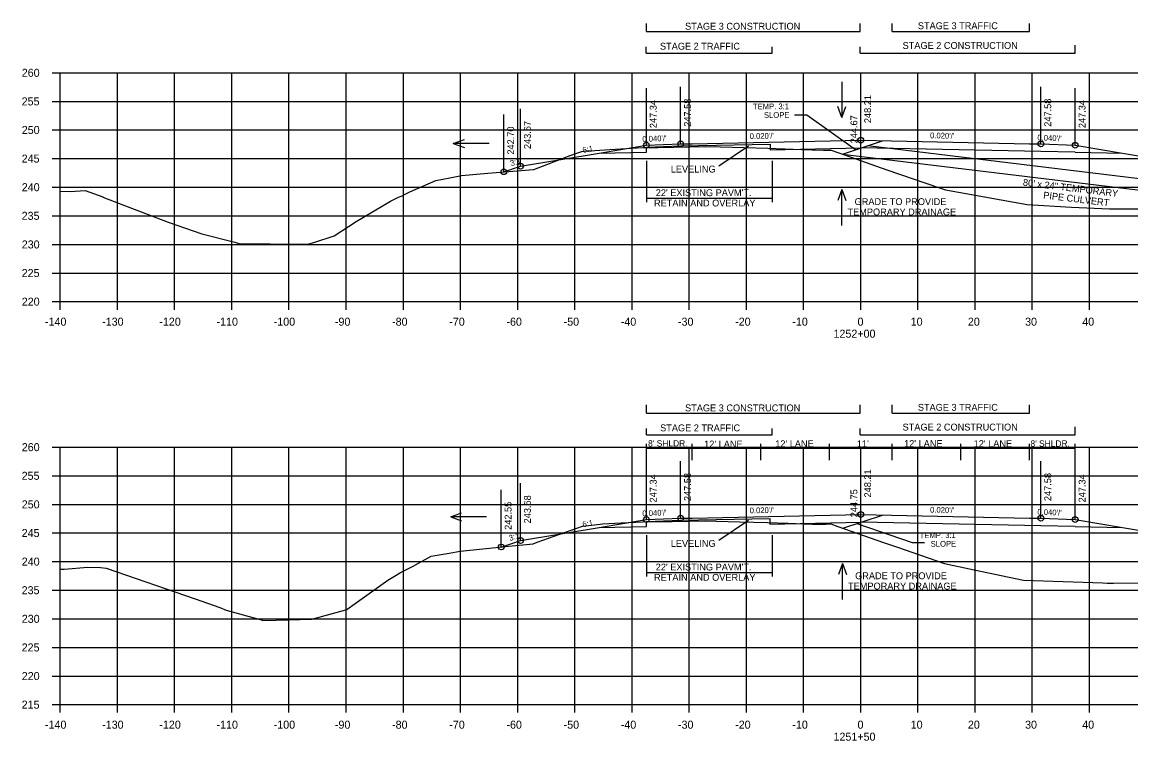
# Model space of a CAD drawing. Extents: x 1342547 to 1344156, y -1532351 to -1517216.
# Drawn here: x 1342556.2 to 1342750.1, y -1527004 to -1526878.4 of the extents above; entities that cross this region are included whole.
import ezdxf

# ---------------------------------------------------------------- set-up
doc = ezdxf.new("R2010")
doc.units = 0
for name, color, linetype in [('R_Alt Surface', 7, 'Continuous'), ('R_Axis', 7, 'Continuous'), ('R_Axis Annot', 7, 'Continuous'), ('R_Draft', 7, 'Continuous'), ('R_Exist Surface', 7, 'Continuous'), ('R_Fin Surface', 7, 'Continuous'), ('R_Grid', 7, 'Continuous'), ('R_No Plot', 7, 'Continuous'), ('R_Water', 7, 'Continuous'), ('R_Xsect Elev', 7, 'Continuous'), ('R_Xsect Slope', 7, 'Continuous')]:
    doc.layers.add(name, color=color, linetype=linetype)

msp = doc.modelspace()

# ---------------------------------------------------------------- linework, layer by layer
at = {"layer": 'R_Alt Surface'}
for points in [[(1342665.37, -1526901.15), (1342665.37, -1526900.27), (1342671.37, -1526900.03), (1342687, -1526899.72)], [(1342687, -1526899.72), (1342687, -1526900.72), (1342702.87, -1526900.4)], [(1342740.37, -1526901.15), (1342734.37, -1526901.03), (1342702.87, -1526900.4)], [(1342657.09, -1526901.31), (1342665.37, -1526901.15)], [(1342740.37, -1526901.15), (1342748.64, -1526901.31)], [(1342657.09, -1526966.73), (1342665.37, -1526966.57)], [(1342665.37, -1526966.57), (1342665.37, -1526965.69), (1342671.37, -1526965.45), (1342686.99, -1526965.14)], [(1342686.99, -1526965.14), (1342686.99, -1526966.14), (1342702.87, -1526965.82)], [(1342740.37, -1526966.57), (1342734.37, -1526966.45), (1342702.87, -1526965.82)], [(1342740.37, -1526966.57), (1342748.64, -1526966.73)]]:
    msp.add_lwpolyline(points, dxfattribs=at)
at = {"layer": 'R_Axis'}
for p, q in [((1342561.47, -1526887.27), (1342562.87, -1526887.27)), ((1342562.87, -1526927.27), (1342562.87, -1526887.27)), ((1342561.47, -1526892.27), (1342562.87, -1526892.27)), ((1342561.47, -1526897.27), (1342562.87, -1526897.27)), ((1342561.47, -1526902.27), (1342562.87, -1526902.27)), ((1342561.47, -1526907.27), (1342562.87, -1526907.27)), ((1342561.47, -1526912.27), (1342562.87, -1526912.27)), ((1342561.47, -1526917.27), (1342562.87, -1526917.27)), ((1342561.47, -1526922.27), (1342562.87, -1526922.27)), ((1342561.47, -1526927.27), (1342562.87, -1526927.27)), ((1342562.87, -1526927.27), (1342842.87, -1526927.27)), ((1342562.87, -1526928.67), (1342562.87, -1526927.27)), ((1342572.87, -1526928.67), (1342572.87, -1526927.27)), ((1342582.87, -1526928.67), (1342582.87, -1526927.27)), ((1342592.87, -1526928.67), (1342592.87, -1526927.27)), ((1342602.87, -1526928.67), (1342602.87, -1526927.27)), ((1342612.87, -1526928.67), (1342612.87, -1526927.27)), ((1342622.87, -1526928.67), (1342622.87, -1526927.27)), ((1342632.87, -1526928.67), (1342632.87, -1526927.27)), ((1342642.87, -1526928.67), (1342642.87, -1526927.27)), ((1342652.87, -1526928.67), (1342652.87, -1526927.27)), ((1342662.87, -1526928.67), (1342662.87, -1526927.27)), ((1342672.87, -1526928.67), (1342672.87, -1526927.27)), ((1342682.87, -1526928.67), (1342682.87, -1526927.27)), ((1342692.87, -1526928.67), (1342692.87, -1526927.27)), ((1342702.87, -1526928.67), (1342702.87, -1526927.27)), ((1342712.87, -1526928.67), (1342712.87, -1526927.27)), ((1342722.87, -1526928.67), (1342722.87, -1526927.27)), ((1342732.87, -1526928.67), (1342732.87, -1526927.27)), ((1342742.87, -1526928.67), (1342742.87, -1526927.27)), ((1342561.47, -1526952.7), (1342562.87, -1526952.7)), ((1342562.87, -1526997.7), (1342562.87, -1526952.7)), ((1342561.47, -1526957.7), (1342562.87, -1526957.7)), ((1342561.47, -1526962.7), (1342562.87, -1526962.7)), ((1342561.47, -1526967.7), (1342562.87, -1526967.7)), ((1342561.47, -1526972.7), (1342562.87, -1526972.7)), ((1342561.47, -1526977.7), (1342562.87, -1526977.7)), ((1342561.47, -1526982.7), (1342562.87, -1526982.7)), ((1342561.47, -1526987.7), (1342562.87, -1526987.7)), ((1342561.47, -1526992.7), (1342562.87, -1526992.7)), ((1342561.47, -1526997.7), (1342562.87, -1526997.7)), ((1342562.87, -1526997.7), (1342842.87, -1526997.7)), ((1342562.87, -1526999.1), (1342562.87, -1526997.7)), ((1342572.87, -1526999.1), (1342572.87, -1526997.7)), ((1342582.87, -1526999.1), (1342582.87, -1526997.7)), ((1342592.87, -1526999.1), (1342592.87, -1526997.7)), ((1342602.87, -1526999.1), (1342602.87, -1526997.7)), ((1342612.87, -1526999.1), (1342612.87, -1526997.7)), ((1342622.87, -1526999.1), (1342622.87, -1526997.7)), ((1342632.87, -1526999.1), (1342632.87, -1526997.7)), ((1342642.87, -1526999.1), (1342642.87, -1526997.7)), ((1342652.87, -1526999.1), (1342652.87, -1526997.7)), ((1342662.87, -1526999.1), (1342662.87, -1526997.7)), ((1342672.87, -1526999.1), (1342672.87, -1526997.7)), ((1342682.87, -1526999.1), (1342682.87, -1526997.7)), ((1342692.87, -1526999.1), (1342692.87, -1526997.7)), ((1342702.87, -1526999.1), (1342702.87, -1526997.7)), ((1342712.87, -1526999.1), (1342712.87, -1526997.7)), ((1342722.87, -1526999.1), (1342722.87, -1526997.7)), ((1342732.87, -1526999.1), (1342732.87, -1526997.7)), ((1342742.87, -1526999.1), (1342742.87, -1526997.7))]:
    msp.add_line(p, q, dxfattribs=at)
at = {"layer": 'R_Draft'}
for p, q in [((1342665.37, -1526880.06), (1342665.37, -1526878.63)), ((1342702.78, -1526880.06), (1342702.78, -1526878.63)), ((1342708.37, -1526880.06), (1342708.37, -1526878.63)), ((1342732.37, -1526880.06), (1342732.37, -1526878.63)), ((1342665.37, -1526880.06), (1342702.78, -1526880.06)), ((1342708.37, -1526880.06), (1342732.37, -1526880.06)), ((1342665.35, -1526883.86), (1342665.35, -1526882.71)), ((1342687.35, -1526883.86), (1342687.35, -1526882.71)), ((1342702.78, -1526883.86), (1342702.78, -1526882.71)), ((1342740.38, -1526883.86), (1342740.38, -1526882.43)), ((1342665.35, -1526883.86), (1342687.35, -1526883.86)), ((1342702.78, -1526883.86), (1342740.38, -1526883.86)), ((1342699.66, -1526901.47), (1342706.64, -1526899.14)), ((1342665.37, -1526902.67), (1342665.37, -1526909.86)), ((1342687.37, -1526902.67), (1342687.37, -1526909.86)), ((1342665.37, -1526909.19), (1342687.37, -1526909.19)), ((1342665.37, -1526946.76), (1342665.37, -1526945.33)), ((1342702.78, -1526946.76), (1342702.78, -1526945.33)), ((1342708.37, -1526946.76), (1342708.37, -1526945.33)), ((1342732.37, -1526946.76), (1342732.37, -1526945.33)), ((1342665.37, -1526946.76), (1342702.78, -1526946.76)), ((1342708.37, -1526946.76), (1342732.37, -1526946.76)), ((1342740.38, -1526950.56), (1342740.38, -1526949.13)), ((1342665.38, -1526950.56), (1342665.38, -1526949.41)), ((1342665.38, -1526950.56), (1342687.38, -1526950.56)), ((1342687.38, -1526950.56), (1342687.38, -1526949.41)), ((1342702.78, -1526950.56), (1342702.78, -1526949.41)), ((1342702.78, -1526950.56), (1342740.38, -1526950.56)), ((1342699.75, -1526966.86), (1342706.64, -1526964.56)), ((1342665.37, -1526968.09), (1342665.37, -1526975.28)), ((1342687.37, -1526968.09), (1342687.37, -1526975.28)), ((1342665.37, -1526974.61), (1342687.37, -1526974.61))]:
    msp.add_line(p, q, dxfattribs=at)
at = {"layer": 'R_Exist Surface'}
for points in [[(1342562.87, -1526907.96), (1342564.58, -1526907.99), (1342567.25, -1526907.87), (1342570.29, -1526908.97), (1342570.29, -1526908.98), (1342581.77, -1526913.38), (1342587.63, -1526915.43), (1342593.39, -1526916.9), (1342594.1, -1526917.1), (1342605.12, -1526917.21), (1342606.35, -1526917.18), (1342607.21, -1526916.95), (1342610.76, -1526915.78), (1342614.64, -1526913.24), (1342620.61, -1526909.72), (1342622.05, -1526909), (1342622.69, -1526908.76), (1342623.09, -1526908.53), (1342624.03, -1526908.06), (1342628.58, -1526906.07), (1342630.99, -1526905.62), (1342633.06, -1526905.24), (1342637.62, -1526904.79), (1342645.7, -1526904.18), (1342652.07, -1526901.74), (1342654.07, -1526901.03), (1342654.92, -1526900.94), (1342655.47, -1526900.91), (1342657.25, -1526900.79), (1342658.98, -1526900.69), (1342664.82, -1526900.33), (1342667.41, -1526900.3), (1342675.69, -1526900.17), (1342678.35, -1526900.24), (1342686.61, -1526900.47), (1342692.54, -1526900.69), (1342694.36, -1526900.75), (1342696.35, -1526900.78), (1342697.7, -1526900.78), (1342700.01, -1526901.59), (1342707.4, -1526904.21), (1342716.61, -1526907.4), (1342717.69, -1526907.72), (1342719.93, -1526908.11), (1342731.94, -1526910.27), (1342739.7, -1526910.77), (1342746.35, -1526911.04), (1342766.34, -1526911.02)], [(1342562.87, -1526974.05), (1342563.12, -1526974.02), (1342563.53, -1526974.01), (1342567.69, -1526973.69), (1342569.93, -1526973.73), (1342570.9, -1526973.86), (1342586.46, -1526979.2), (1342590.75, -1526980.74), (1342591.89, -1526981.18), (1342598.25, -1526982.96), (1342598.31, -1526982.98), (1342600.57, -1526982.93), (1342606.84, -1526982.77), (1342612.79, -1526981.12), (1342612.93, -1526981.08), (1342613.37, -1526980.79), (1342614.03, -1526980.33), (1342620.18, -1526975.94), (1342621.3, -1526975.24), (1342622.4, -1526974.6), (1342624.5, -1526973.54), (1342627.73, -1526971.77), (1342630.87, -1526971.22), (1342632.82, -1526970.86), (1342641.3, -1526970.02), (1342645.55, -1526969.58), (1342646.28, -1526969.32), (1342654.19, -1526966.5), (1342657.31, -1526966.16), (1342657.7, -1526966.11), (1342660.96, -1526965.94), (1342664.72, -1526965.75), (1342669.88, -1526965.68), (1342675.67, -1526965.6), (1342681.65, -1526965.76), (1342686.55, -1526965.89), (1342690.11, -1526966.01), (1342694.44, -1526966.16), (1342695.62, -1526966.15), (1342696.48, -1526966.14), (1342696.82, -1526966.14), (1342697.64, -1526966.11), (1342698.85, -1526966.54), (1342706.84, -1526969.35), (1342709.14, -1526970.11), (1342717.53, -1526973.03), (1342722.7, -1526974.16), (1342731.3, -1526975.92), (1342745.22, -1526976.42), (1342745.94, -1526976.45), (1342747.08, -1526976.44), (1342778.45, -1526976.41)]]:
    msp.add_lwpolyline(points, dxfattribs=at)
at = {"layer": 'R_Fin Surface'}
for points in [[(1342640.45, -1526904.57), (1342643.37, -1526903.6), (1342657.09, -1526901.31), (1342665.37, -1526899.94), (1342671.37, -1526899.7), (1342673.37, -1526899.66), (1342702.87, -1526899.07), (1342732.37, -1526899.66), (1342734.37, -1526899.7), (1342740.37, -1526899.94), (1342748.64, -1526901.31), (1342762.37, -1526903.6), (1342784.49, -1526910.98)], [(1342639.99, -1526970.15), (1342643.37, -1526969.02), (1342657.09, -1526966.73), (1342665.37, -1526965.36), (1342671.37, -1526965.12), (1342673.37, -1526965.08), (1342702.87, -1526964.49), (1342732.37, -1526965.08), (1342734.37, -1526965.12), (1342740.37, -1526965.36), (1342748.64, -1526966.73), (1342762.37, -1526969.02), (1342784.52, -1526976.41)]]:
    msp.add_lwpolyline(points, dxfattribs=at)
at = {"layer": 'R_Grid'}
for p, q in [((1342562.87, -1526887.27), (1342842.87, -1526887.27)), ((1342562.87, -1526927.27), (1342562.87, -1526887.27)), ((1342572.87, -1526927.27), (1342572.87, -1526887.27)), ((1342582.87, -1526927.27), (1342582.87, -1526887.27)), ((1342592.87, -1526927.27), (1342592.87, -1526887.27)), ((1342602.87, -1526927.27), (1342602.87, -1526887.27)), ((1342612.87, -1526927.27), (1342612.87, -1526887.27)), ((1342622.87, -1526927.27), (1342622.87, -1526887.27)), ((1342632.87, -1526927.27), (1342632.87, -1526887.27)), ((1342642.87, -1526927.27), (1342642.87, -1526887.27)), ((1342652.87, -1526927.27), (1342652.87, -1526887.27)), ((1342662.87, -1526927.27), (1342662.87, -1526887.27)), ((1342672.87, -1526927.27), (1342672.87, -1526887.27)), ((1342682.87, -1526927.27), (1342682.87, -1526887.27)), ((1342692.87, -1526927.27), (1342692.87, -1526887.27)), ((1342702.87, -1526927.27), (1342702.87, -1526887.27)), ((1342712.87, -1526927.27), (1342712.87, -1526887.27)), ((1342722.87, -1526927.27), (1342722.87, -1526887.27)), ((1342732.87, -1526927.27), (1342732.87, -1526887.27)), ((1342742.87, -1526927.27), (1342742.87, -1526887.27)), ((1342562.87, -1526892.27), (1342842.87, -1526892.27)), ((1342562.87, -1526897.27), (1342842.87, -1526897.27)), ((1342562.87, -1526902.27), (1342842.87, -1526902.27)), ((1342562.87, -1526907.27), (1342842.87, -1526907.27)), ((1342562.87, -1526912.27), (1342842.87, -1526912.27)), ((1342562.87, -1526917.27), (1342842.87, -1526917.27)), ((1342562.87, -1526922.27), (1342842.87, -1526922.27)), ((1342562.87, -1526927.27), (1342842.87, -1526927.27)), ((1342562.87, -1526952.7), (1342842.87, -1526952.7)), ((1342562.87, -1526997.7), (1342562.87, -1526952.7)), ((1342572.87, -1526997.7), (1342572.87, -1526952.7)), ((1342582.87, -1526997.7), (1342582.87, -1526952.7)), ((1342592.87, -1526997.7), (1342592.87, -1526952.7)), ((1342602.87, -1526997.7), (1342602.87, -1526952.7)), ((1342612.87, -1526997.7), (1342612.87, -1526952.7)), ((1342622.87, -1526997.7), (1342622.87, -1526952.7)), ((1342632.87, -1526997.7), (1342632.87, -1526952.7)), ((1342642.87, -1526997.7), (1342642.87, -1526952.7)), ((1342652.87, -1526997.7), (1342652.87, -1526952.7)), ((1342662.87, -1526997.7), (1342662.87, -1526952.7)), ((1342672.87, -1526997.7), (1342672.87, -1526952.7)), ((1342682.87, -1526997.7), (1342682.87, -1526952.7)), ((1342692.87, -1526997.7), (1342692.87, -1526952.7)), ((1342702.87, -1526997.7), (1342702.87, -1526952.7)), ((1342712.87, -1526997.7), (1342712.87, -1526952.7)), ((1342722.87, -1526997.7), (1342722.87, -1526952.7)), ((1342732.87, -1526997.7), (1342732.87, -1526952.7)), ((1342742.87, -1526997.7), (1342742.87, -1526952.7)), ((1342562.87, -1526957.7), (1342842.87, -1526957.7)), ((1342562.87, -1526962.7), (1342842.87, -1526962.7)), ((1342562.87, -1526967.7), (1342842.87, -1526967.7)), ((1342562.87, -1526972.7), (1342842.87, -1526972.7)), ((1342562.87, -1526977.7), (1342842.87, -1526977.7)), ((1342562.87, -1526982.7), (1342842.87, -1526982.7)), ((1342562.87, -1526987.7), (1342842.87, -1526987.7)), ((1342562.87, -1526992.7), (1342842.87, -1526992.7)), ((1342562.87, -1526997.7), (1342842.87, -1526997.7))]:
    msp.add_line(p, q, dxfattribs=at)
at = {"layer": 'R_No Plot'}
for centre in [(1342702.87, -1526899.07), (1342665.37, -1526899.94), (1342671.37, -1526899.7), (1342734.37, -1526899.7), (1342740.37, -1526899.94), (1342640.45, -1526904.57), (1342643.37, -1526903.6), (1342671.37, -1526965.12), (1342702.87, -1526964.49), (1342734.37, -1526965.12), (1342665.37, -1526965.36), (1342740.37, -1526965.36), (1342643.37, -1526969.02), (1342639.99, -1526970.15)]:
    msp.add_circle(centre, 0.5, dxfattribs=at)
at = {"layer": 'R_Water'}
for p, q in [((1342699.56, -1526888.83), (1342699.56, -1526895.11)), ((1342699.56, -1526895.11), (1342698.86, -1526893.19)), ((1342699.56, -1526895.11), (1342700.26, -1526893.19)), ((1342631.61, -1526899.62), (1342633.54, -1526898.92)), ((1342637.9, -1526899.62), (1342631.61, -1526899.62)), ((1342631.61, -1526899.62), (1342633.54, -1526900.32)), ((1342699.56, -1526907.66), (1342698.86, -1526909.58)), ((1342699.56, -1526913.94), (1342699.56, -1526907.66)), ((1342699.56, -1526907.66), (1342700.26, -1526909.58)), ((1342631.15, -1526964.86), (1342633.07, -1526964.16)), ((1342637.44, -1526964.86), (1342631.15, -1526964.86)), ((1342631.15, -1526964.86), (1342633.07, -1526965.56)), ((1342699.65, -1526973.05), (1342698.95, -1526974.97)), ((1342699.65, -1526979.33), (1342699.65, -1526973.05)), ((1342699.65, -1526973.05), (1342700.35, -1526974.97))]:
    msp.add_line(p, q, dxfattribs=at)
for points in [[(1342704.09, -1526899.99), (1342778.5, -1526909.02)], [(1342699.66, -1526901.47), (1342778.26, -1526911.01)]]:
    msp.add_lwpolyline(points, dxfattribs=at)
at = {"layer": 'R_Xsect Elev'}
for p, q in [((1342702.87, -1526899.07), (1342702.87, -1526889.07)), ((1342665.37, -1526899.94), (1342665.37, -1526889.94)), ((1342671.37, -1526899.7), (1342671.37, -1526889.7)), ((1342734.37, -1526899.7), (1342734.37, -1526889.7)), ((1342740.37, -1526899.94), (1342740.37, -1526889.94)), ((1342702.87, -1526902.6), (1342702.87, -1526892.6)), ((1342640.45, -1526904.57), (1342640.45, -1526894.57)), ((1342643.37, -1526903.6), (1342643.37, -1526893.6)), ((1342693.43, -1526894.66), (1342691.29, -1526894.66)), ((1342701.96, -1526900.74), (1342693.43, -1526894.66)), ((1342683.22, -1526900.08), (1342678.02, -1526903.57)), ((1342665.37, -1526965.36), (1342665.37, -1526952.1)), ((1342740.37, -1526952.96), (1342665.37, -1526952.96)), ((1342673.37, -1526954.97), (1342673.37, -1526952.1)), ((1342685.37, -1526954.97), (1342685.37, -1526952.1)), ((1342697.37, -1526954.97), (1342697.37, -1526952.1)), ((1342708.37, -1526954.97), (1342708.37, -1526952.1)), ((1342720.37, -1526954.97), (1342720.37, -1526952.1)), ((1342732.37, -1526954.97), (1342732.37, -1526952.1)), ((1342740.37, -1526965.36), (1342740.37, -1526952.1)), ((1342702.87, -1526964.49), (1342702.87, -1526954.49)), ((1342665.37, -1526965.36), (1342665.37, -1526955.36)), ((1342665.37, -1526965.36), (1342665.37, -1526955.36)), ((1342671.37, -1526965.12), (1342671.37, -1526955.12)), ((1342734.37, -1526965.12), (1342734.37, -1526955.12)), ((1342740.37, -1526965.36), (1342740.37, -1526955.36)), ((1342740.37, -1526965.36), (1342740.37, -1526955.36)), ((1342702.87, -1526967.95), (1342702.87, -1526957.95)), ((1342639.99, -1526970.15), (1342639.99, -1526960.15)), ((1342643.37, -1526969.02), (1342643.37, -1526959.02)), ((1342683.22, -1526965.51), (1342678.02, -1526968.99)), ((1342702.16, -1526966.05), (1342711.85, -1526969.35)), ((1342711.85, -1526969.35), (1342713.99, -1526969.35))]:
    msp.add_line(p, q, dxfattribs=at)

# ---------------------------------------------------------------- texts
at = {"layer": 'R_Axis Annot'}
for s, p in [('260', (1342556.14, -1526887.97)), ('255', (1342556.12, -1526892.97)), ('250', (1342556.14, -1526897.97)), ('245', (1342556.12, -1526902.97)), ('240', (1342556.14, -1526907.97)), ('235', (1342556.12, -1526912.97)), ('230', (1342556.14, -1526917.97)), ('225', (1342556.12, -1526922.97)), ('220', (1342556.14, -1526927.97)), ('-140', (1342560.2, -1526931.47)), ('-130', (1342570.2, -1526931.47)), ('-120', (1342580.2, -1526931.47)), ('-110', (1342590.2, -1526931.47)), ('-100', (1342600.2, -1526931.47)), ('-90', (1342610.9, -1526931.47)), ('-80', (1342620.9, -1526931.47)), ('-70', (1342630.9, -1526931.47)), ('-60', (1342640.9, -1526931.47)), ('-50', (1342650.9, -1526931.47)), ('-40', (1342660.9, -1526931.47)), ('-30', (1342670.9, -1526931.47)), ('-20', (1342680.9, -1526931.47)), ('-10', (1342690.9, -1526931.47)), ('0', (1342702.3, -1526931.47)), ('10', (1342711.6, -1526931.47)), ('20', (1342721.6, -1526931.47)), ('30', (1342731.6, -1526931.47)), ('40', (1342741.6, -1526931.47)), ('1252+00', (1342698.1, -1526933.57)), ('260', (1342556.14, -1526953.4)), ('255', (1342556.12, -1526958.4)), ('250', (1342556.14, -1526963.4)), ('245', (1342556.12, -1526968.4)), ('240', (1342556.14, -1526973.4)), ('235', (1342556.12, -1526978.4)), ('230', (1342556.14, -1526983.4)), ('225', (1342556.12, -1526988.4)), ('220', (1342556.14, -1526993.4)), ('215', (1342556.12, -1526998.4)), ('-140', (1342560.2, -1527001.9)), ('-130', (1342570.2, -1527001.9)), ('-120', (1342580.2, -1527001.9)), ('-110', (1342590.2, -1527001.9)), ('-100', (1342600.2, -1527001.9)), ('-90', (1342610.9, -1527001.9)), ('-80', (1342620.9, -1527001.9)), ('-70', (1342630.9, -1527001.9)), ('-60', (1342640.9, -1527001.9)), ('-50', (1342650.9, -1527001.9)), ('-40', (1342660.9, -1527001.9)), ('-30', (1342670.9, -1527001.9)), ('-20', (1342680.9, -1527001.9)), ('-10', (1342690.9, -1527001.9)), ('0', (1342702.3, -1527001.9)), ('10', (1342711.6, -1527001.9)), ('20', (1342721.6, -1527001.9)), ('30', (1342731.6, -1527001.9)), ('40', (1342741.6, -1527001.9)), ('1251+50', (1342698.1, -1527004))]:
    msp.add_text(s, height=1.4, dxfattribs=at).set_placement(p)
at = {"layer": 'R_Draft'}
for s, p in [('STAGE 3 CONSTRUCTION', (1342672.14, -1526879.74)), ('STAGE 3 TRAFFIC', (1342712.85, -1526879.65)), ('STAGE 2 TRAFFIC', (1342667.75, -1526883.23)), ('STAGE 2 CONSTRUCTION', (1342710.18, -1526883.1)), ("22' EXISTING PAVM'T.", (1342667.01, -1526908.83)), ('RETAIN AND OVERLAY', (1342666.71, -1526910.63)), ('STAGE 3 CONSTRUCTION', (1342672.14, -1526946.44)), ('STAGE 3 TRAFFIC', (1342712.85, -1526946.34)), ('STAGE 2 TRAFFIC', (1342667.78, -1526949.93)), ('STAGE 2 CONSTRUCTION', (1342710.18, -1526949.79)), ("22' EXISTING PAVM'T.", (1342667.01, -1526974.25)), ('RETAIN AND OVERLAY', (1342666.71, -1526976.05))]:
    msp.add_text(s, height=1.2, dxfattribs=at).set_placement(p)
at = {"layer": 'R_Water'}
for s, rotation, p in [('80\' x 24" TEMPORARY', 353.1274, (1342731.17, -1526906.98)), ('PIPE CULVERT', 353.1274, (1342734.73, -1526909.22)), ('GRADE TO PROVIDE', 359.9909, (1342701.79, -1526910.39)), ('TEMPORARY DRAINAGE', 359.9909, (1342700.55, -1526912.19)), ('TEMPORARY DRAINAGE', 359.9909, (1342700.64, -1526977.58)), ('GRADE TO PROVIDE', 359.9909, (1342701.88, -1526975.78))]:
    msp.add_text(s, height=1.2, rotation=rotation, dxfattribs=at).set_placement(p)
at = {"layer": 'R_Xsect Elev'}
for s, p in [('247.34', (1342667.17, -1526896.94)), ('247.58', (1342673.17, -1526896.7)), ('248.21', (1342704.67, -1526896.07)), ('247.58', (1342736.17, -1526896.7)), ('247.34', (1342742.17, -1526896.94)), ('244.67', (1342702.27, -1526899.6)), ('242.70', (1342642.25, -1526901.57)), ('243.67', (1342645.17, -1526900.6)), ('248.21', (1342704.67, -1526961.49)), ('247.34', (1342667.17, -1526962.36)), ('247.58', (1342673.17, -1526962.12)), ('247.58', (1342736.17, -1526962.12)), ('247.34', (1342742.17, -1526962.36)), ('244.75', (1342702.27, -1526964.95)), ('242.55', (1342641.79, -1526967.15)), ('243.68', (1342645.17, -1526966.02))]:
    msp.add_text(s, height=1.2, rotation=90, dxfattribs=at).set_placement(p)
for s, height, p in [('LEVELING', 1.2, (1342669.64, -1526904.7)), ("8' SHLDR.", 1.1, (1342665.67, -1526952.58)), ("12' LANE", 1.2, (1342675.48, -1526952.75)), ("12' LANE", 1.2, (1342687.91, -1526952.7)), ("11'", 1.2, (1342702.18, -1526952.7)), ("12' LANE", 1.2, (1342710.44, -1526952.67)), ("12' LANE", 1.2, (1342722.61, -1526952.68)), ("8' SHLDR.", 1.1, (1342732.54, -1526952.62)), ('LEVELING', 1.2, (1342669.64, -1526970.12))]:
    msp.add_text(s, height=height, dxfattribs=at).set_placement(p)
at = {"layer": 'R_Xsect Slope'}
for s, rotation, p in [('TEMP. 3:1', 0.3758, (1342684.01, -1526893.67)), ('SLOPE', 0.3758, (1342685.94, -1526895.16)), ("0.040'/'", 2.2906, (1342664.69, -1526899.36)), ("0.020'/'", 1.1458, (1342683.45, -1526898.85)), ("0.020'/'", 358.8542, (1342714.98, -1526898.71)), ("0.040'/'", 357.7092, (1342733.74, -1526899.07)), ('6:1', 9.4623, (1342654.28, -1526901.28)), ('3:1', 18.4349, (1342641.75, -1526903.61)), ("0.040'/'", 2.2906, (1342664.69, -1526964.78)), ("0.020'/'", 1.1458, (1342683.45, -1526964.27)), ("0.020'/'", 358.8542, (1342714.98, -1526964.13)), ("0.040'/'", 357.7092, (1342733.74, -1526964.49)), ('6:1', 9.4623, (1342654.28, -1526966.7)), ('3:1', 18.4349, (1342641.52, -1526969.11)), ('TEMP. 3:1', 0.3758, (1342713.17, -1526968.61)), ('SLOPE', 0.3758, (1342715.1, -1526970.1))]:
    msp.add_text(s, height=1, rotation=rotation, dxfattribs=at).set_placement(p)

doc.saveas('drawing.dxf')
